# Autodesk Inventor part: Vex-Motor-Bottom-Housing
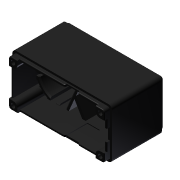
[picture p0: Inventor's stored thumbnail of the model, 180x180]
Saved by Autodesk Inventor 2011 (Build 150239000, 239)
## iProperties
Created: 2007-08
Part Number: Vex-Motor-Bottom-Housing
Material: ABS Plastic
Document SubType Name: Modeling
Density: 1.06 g/cm^3
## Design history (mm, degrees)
feature "Base1"
body "Solid1"
